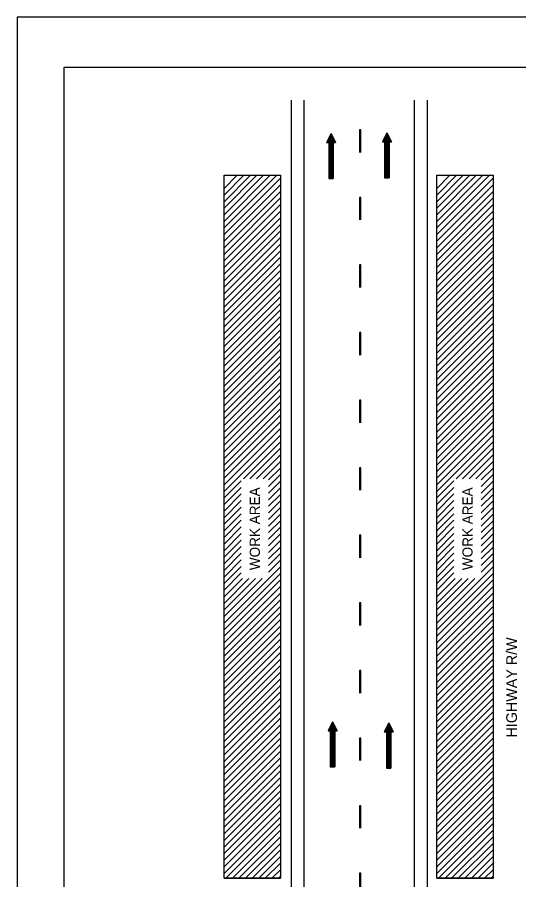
# Model space of a CAD drawing. Extents: x 1351 to 1567, y 178 to 457.
# Drawn here: x 1351.4 to 1459, y 271.7 to 456.9 of the extents above; entities that cross this region are included whole.
import ezdxf

# ---------------------------------------------------------------- set-up
doc = ezdxf.new("R2010")
doc.units = 0
for name, color, linetype in [('Level 10', 7, 'Continuous'), ('Level 2', 7, 'Continuous'), ('Level 60', 7, 'Continuous')]:
    doc.layers.add(name, color=color, linetype=linetype)

# ---------------------------------------------------------------- blocks, each defined once
blk = doc.blocks.new('C_LINE')
at = {"layer": 'Level 2'}
for p, q in [((-0.145, 237.062), (-0.145, 232.224)), ((0.145, 237.062), (-0.145, 237.062)), ((0.145, 232.224), (0.145, 237.062)), ((-0.145, 222.548), (-0.145, 217.71)), ((0.145, 222.548), (-0.145, 222.548)), ((0.145, 217.71), (0.145, 222.548)), ((-0.145, 208.034), (-0.145, 203.196)), ((0.145, 208.034), (-0.145, 208.034)), ((0.145, 203.196), (0.145, 208.034)), ((-0.145, 193.52), (-0.145, 188.682)), ((0.145, 193.52), (-0.145, 193.52)), ((0.145, 188.682), (0.145, 193.52)), ((-0.145, 179.006), (-0.145, 174.168)), ((0.145, 179.006), (-0.145, 179.006)), ((0.145, 174.168), (0.145, 179.006)), ((-0.145, 164.492), (-0.145, 159.654)), ((0.145, 164.492), (-0.145, 164.492)), ((0.145, 159.654), (0.145, 164.492)), ((-0.145, 149.978), (-0.145, 145.14)), ((0.145, 149.978), (-0.145, 149.978)), ((0.145, 145.14), (0.145, 149.978)), ((-0.145, 135.464), (-0.145, 130.626)), ((0.145, 135.464), (-0.145, 135.464)), ((0.145, 130.626), (0.145, 135.464)), ((-0.145, 120.95), (-0.145, 116.112)), ((0.145, 120.95), (-0.145, 120.95)), ((0.145, 116.112), (0.145, 120.95)), ((-0.145, 106.436), (-0.145, 101.598)), ((0.145, 106.436), (-0.145, 106.436)), ((0.145, 101.598), (0.145, 106.436)), ((-0.145, 91.922), (-0.145, 87.084)), ((0.145, 91.922), (-0.145, 91.922)), ((0.145, 87.084), (0.145, 91.922)), ((-0.145, 77.408), (-0.145, 72.57)), ((0.145, 77.408), (-0.145, 77.408)), ((0.145, 72.57), (0.145, 77.408))]:
    blk.add_line(p, q, dxfattribs=at)

msp = doc.modelspace()

# ---------------------------------------------------------------- linework, layer by layer
at = {"layer": 'Level 10'}
for p, q in [((1410.15, 439.12), (1410.15, 193.22)), ((1412.88, 439.12), (1412.88, 193.22)), ((1436.58, 439.12), (1436.58, 193.22)), ((1439.33, 439.12), (1439.33, 193.22)), ((1418.72, 431.99), (1417.75, 430.06)), ((1418.6, 431.75), (1418.6, 422.31)), ((1418.72, 431.99), (1418.72, 422.31)), ((1418.72, 431.99), (1419.68, 430.06)), ((1418.84, 431.75), (1418.84, 422.31)), ((1430.7, 432.12), (1429.74, 430.18)), ((1430.46, 431.63), (1430.46, 422.44)), ((1430.58, 431.87), (1430.58, 422.44)), ((1430.7, 432.12), (1430.7, 422.44)), ((1430.7, 432.12), (1431.67, 430.18)), ((1430.82, 431.87), (1430.82, 422.44)), ((1430.94, 431.63), (1430.94, 422.44)), ((1417.75, 430.06), (1418.23, 430.06)), ((1417.87, 430.3), (1417.87, 430.06)), ((1417.99, 430.54), (1417.99, 430.06)), ((1418.11, 430.78), (1418.11, 430.06)), ((1418.23, 431.02), (1418.23, 422.31)), ((1418.23, 430.06), (1418.23, 422.31)), ((1418.35, 431.26), (1418.35, 422.31)), ((1418.48, 431.51), (1418.48, 422.31)), ((1418.96, 431.51), (1418.96, 422.31)), ((1419.08, 431.26), (1419.08, 422.31)), ((1419.2, 431.02), (1419.2, 422.31)), ((1419.2, 430.06), (1419.2, 422.31)), ((1419.2, 430.06), (1419.68, 430.06)), ((1419.32, 430.78), (1419.32, 430.06)), ((1419.44, 430.54), (1419.44, 430.06)), ((1419.56, 430.3), (1419.56, 430.06)), ((1429.74, 430.18), (1430.22, 430.18)), ((1429.86, 430.42), (1429.86, 430.18)), ((1429.98, 430.66), (1429.98, 430.18)), ((1430.1, 430.91), (1430.1, 430.18)), ((1430.22, 431.15), (1430.22, 422.44)), ((1430.22, 430.18), (1430.22, 422.44)), ((1430.34, 431.39), (1430.34, 422.44)), ((1431.07, 431.39), (1431.07, 422.44)), ((1431.19, 431.15), (1431.19, 422.44)), ((1431.19, 430.18), (1431.19, 422.44)), ((1431.19, 430.18), (1431.67, 430.18)), ((1431.31, 430.91), (1431.31, 430.18)), ((1431.43, 430.66), (1431.43, 430.18)), ((1431.55, 430.42), (1431.55, 430.18)), ((1395.76, 420.15), (1398.59, 422.98)), ((1395.76, 418.74), (1400, 422.98)), ((1395.76, 417.32), (1401.41, 422.98)), ((1395.76, 415.91), (1402.83, 422.98)), ((1395.76, 414.5), (1404.24, 422.98)), ((1395.76, 413.08), (1405.66, 422.98)), ((1395.76, 411.67), (1407.07, 422.98)), ((1395.76, 410.25), (1407.85, 422.35)), ((1418.23, 422.31), (1419.2, 422.31)), ((1430.22, 422.44), (1431.19, 422.44)), ((1441.38, 420.15), (1444.21, 422.98)), ((1441.38, 418.74), (1445.63, 422.98)), ((1441.38, 417.32), (1447.04, 422.98)), ((1441.38, 415.91), (1448.46, 422.98)), ((1441.38, 414.5), (1449.87, 422.98)), ((1441.38, 413.08), (1451.28, 422.98)), ((1441.38, 411.67), (1452.7, 422.98)), ((1441.38, 410.25), (1453.48, 422.35)), ((1395.76, 408.84), (1407.85, 420.93)), ((1441.38, 408.84), (1453.48, 420.93)), ((1395.76, 407.43), (1407.85, 419.52)), ((1441.38, 407.43), (1453.48, 419.52)), ((1395.76, 406.01), (1407.85, 418.11)), ((1441.38, 406.01), (1453.48, 418.11)), ((1395.76, 404.6), (1407.85, 416.69)), ((1395.76, 403.18), (1407.85, 415.28)), ((1441.38, 404.6), (1453.48, 416.69)), ((1441.38, 403.18), (1453.48, 415.28)), ((1395.76, 401.77), (1407.85, 413.86)), ((1441.38, 401.77), (1453.48, 413.86)), ((1395.76, 400.35), (1407.85, 412.45)), ((1441.38, 400.35), (1453.48, 412.45)), ((1395.76, 398.94), (1407.85, 411.03)), ((1395.76, 397.53), (1407.85, 409.62)), ((1441.38, 398.94), (1453.48, 411.03)), ((1441.38, 397.53), (1453.48, 409.62)), ((1395.76, 396.11), (1407.85, 408.21)), ((1441.38, 396.11), (1453.48, 408.21)), ((1395.76, 394.7), (1407.85, 406.79)), ((1441.38, 394.7), (1453.48, 406.79)), ((1395.76, 393.28), (1407.85, 405.38)), ((1395.76, 391.87), (1407.85, 403.96)), ((1441.38, 393.28), (1453.48, 405.38)), ((1441.38, 391.87), (1453.48, 403.96)), ((1395.76, 390.45), (1407.85, 402.55)), ((1441.38, 390.45), (1453.48, 402.55)), ((1395.76, 389.04), (1407.85, 401.13)), ((1441.38, 389.04), (1453.48, 401.13)), ((1395.76, 387.63), (1407.85, 399.72)), ((1395.76, 386.21), (1407.85, 398.31)), ((1441.38, 387.63), (1453.48, 399.72)), ((1441.38, 386.21), (1453.48, 398.31)), ((1395.76, 384.8), (1407.85, 396.89)), ((1441.38, 384.8), (1453.48, 396.89)), ((1395.76, 383.38), (1407.85, 395.48)), ((1441.38, 383.38), (1453.48, 395.48)), ((1395.76, 381.97), (1407.85, 394.06)), ((1441.38, 381.97), (1453.48, 394.06)), ((1395.76, 380.56), (1407.85, 392.65)), ((1395.76, 379.14), (1407.85, 391.24)), ((1441.38, 380.56), (1453.48, 392.65)), ((1441.38, 379.14), (1453.48, 391.24)), ((1395.76, 377.73), (1407.85, 389.82)), ((1441.38, 377.73), (1453.48, 389.82)), ((1395.76, 376.31), (1407.85, 388.41)), ((1441.38, 376.31), (1453.48, 388.41)), ((1395.76, 374.9), (1407.85, 386.99)), ((1395.76, 373.48), (1407.85, 385.58)), ((1441.38, 374.9), (1453.48, 386.99)), ((1441.38, 373.48), (1453.48, 385.58)), ((1395.76, 372.07), (1407.85, 384.16)), ((1441.38, 372.07), (1453.48, 384.16)), ((1395.76, 370.66), (1407.85, 382.75)), ((1441.38, 370.66), (1453.48, 382.75)), ((1395.76, 369.24), (1407.85, 381.34)), ((1395.76, 367.83), (1407.85, 379.92)), ((1441.38, 369.24), (1453.48, 381.34)), ((1441.38, 367.83), (1453.48, 379.92)), ((1395.76, 366.41), (1407.85, 378.51)), ((1441.38, 366.41), (1453.48, 378.51)), ((1395.76, 365), (1407.85, 377.09)), ((1441.38, 365), (1453.48, 377.09)), ((1395.76, 363.58), (1407.85, 375.68)), ((1395.76, 362.17), (1407.85, 374.26)), ((1441.38, 363.58), (1453.48, 375.68)), ((1441.38, 362.17), (1453.48, 374.26)), ((1395.76, 360.76), (1407.85, 372.85)), ((1441.38, 360.76), (1453.48, 372.85)), ((1395.76, 359.34), (1407.85, 371.44)), ((1441.38, 359.34), (1453.48, 371.44)), ((1395.76, 357.93), (1407.85, 370.02)), ((1395.76, 356.51), (1407.85, 368.61)), ((1441.38, 357.93), (1453.48, 370.02)), ((1441.38, 356.51), (1453.48, 368.61)), ((1395.76, 355.1), (1407.85, 367.19)), ((1441.38, 355.1), (1453.48, 367.19)), ((1399.91, 357.83), (1407.85, 365.78)), ((1445.53, 357.83), (1453.48, 365.78)), ((1401.32, 357.83), (1407.85, 364.37)), ((1446.95, 357.83), (1453.48, 364.37)), ((1402.74, 357.83), (1407.85, 362.95)), ((1404.15, 357.83), (1407.85, 361.54)), ((1448.36, 357.83), (1453.48, 362.95)), ((1449.78, 357.83), (1453.48, 361.54)), ((1405.29, 357.56), (1407.85, 360.12)), ((1450.92, 357.56), (1453.48, 360.12)), ((1405.29, 356.14), (1407.85, 358.71)), ((1450.92, 356.14), (1453.48, 358.71)), ((1395.76, 353.69), (1399.45, 357.38)), ((1395.76, 352.27), (1399.45, 355.97)), ((1405.29, 354.73), (1407.85, 357.29)), ((1405.29, 353.32), (1407.85, 355.88)), ((1441.38, 353.69), (1445.08, 357.38)), ((1441.38, 352.27), (1445.08, 355.97)), ((1450.92, 354.73), (1453.48, 357.29)), ((1450.92, 353.32), (1453.48, 355.88)), ((1395.76, 350.86), (1399.45, 354.55)), ((1405.29, 351.9), (1407.85, 354.47)), ((1441.38, 350.86), (1445.08, 354.55)), ((1450.92, 351.9), (1453.48, 354.47)), ((1395.76, 349.44), (1399.45, 353.14)), ((1405.29, 350.49), (1407.85, 353.05)), ((1441.38, 349.44), (1445.08, 353.14)), ((1450.92, 350.49), (1453.48, 353.05)), ((1395.76, 348.03), (1399.45, 351.73)), ((1395.76, 346.61), (1399.45, 350.31)), ((1405.29, 349.07), (1407.85, 351.64)), ((1405.29, 347.66), (1407.85, 350.22)), ((1441.38, 348.03), (1445.08, 351.73)), ((1441.38, 346.61), (1445.08, 350.31)), ((1450.92, 349.07), (1453.48, 351.64)), ((1450.92, 347.66), (1453.48, 350.22)), ((1395.76, 345.2), (1399.45, 348.9)), ((1405.29, 346.25), (1407.85, 348.81)), ((1441.38, 345.2), (1445.08, 348.9)), ((1450.92, 346.25), (1453.48, 348.81)), ((1395.76, 343.79), (1399.45, 347.48)), ((1405.29, 344.83), (1407.85, 347.39)), ((1441.38, 343.79), (1445.08, 347.48)), ((1450.92, 344.83), (1453.48, 347.39)), ((1395.76, 342.37), (1399.45, 346.07)), ((1395.76, 340.96), (1399.45, 344.65)), ((1405.29, 343.42), (1407.85, 345.98)), ((1405.29, 342), (1407.85, 344.57)), ((1441.38, 342.37), (1445.08, 346.07)), ((1441.38, 340.96), (1445.08, 344.65)), ((1450.92, 343.42), (1453.48, 345.98)), ((1450.92, 342), (1453.48, 344.57)), ((1395.76, 339.54), (1399.45, 343.24)), ((1405.29, 340.59), (1407.85, 343.15)), ((1441.38, 339.54), (1445.08, 343.24)), ((1450.92, 340.59), (1453.48, 343.15)), ((1395.76, 338.13), (1399.45, 341.82)), ((1405.29, 339.18), (1407.85, 341.74)), ((1441.38, 338.13), (1445.08, 341.82)), ((1450.92, 339.18), (1453.48, 341.74)), ((1395.76, 336.71), (1399.45, 340.41)), ((1395.76, 335.3), (1399.45, 339)), ((1405.29, 337.76), (1407.85, 340.32)), ((1441.38, 336.71), (1445.08, 340.41)), ((1441.38, 335.3), (1445.08, 339)), ((1450.92, 337.76), (1453.48, 340.32)), ((1395.76, 326.81), (1407.85, 338.91)), ((1395.76, 333.89), (1399.45, 337.58)), ((1395.76, 325.4), (1407.85, 337.5)), ((1441.38, 326.81), (1453.48, 338.91)), ((1441.38, 333.89), (1445.08, 337.58)), ((1441.38, 325.4), (1453.48, 337.5)), ((1395.76, 332.47), (1399.7, 336.41)), ((1395.76, 331.06), (1401.11, 336.41)), ((1395.76, 329.64), (1402.53, 336.41)), ((1395.76, 328.23), (1403.94, 336.41)), ((1395.76, 323.99), (1407.85, 336.08)), ((1441.38, 332.47), (1445.33, 336.41)), ((1441.38, 331.06), (1446.74, 336.41)), ((1441.38, 329.64), (1448.16, 336.41)), ((1441.38, 328.23), (1449.57, 336.41)), ((1441.38, 323.99), (1453.48, 336.08)), ((1395.76, 322.57), (1407.85, 334.67)), ((1441.38, 322.57), (1453.48, 334.67)), ((1395.76, 321.16), (1407.85, 333.25)), ((1395.76, 319.74), (1407.85, 331.84)), ((1441.38, 321.16), (1453.48, 333.25)), ((1441.38, 319.74), (1453.48, 331.84)), ((1395.76, 318.33), (1407.85, 330.42)), ((1441.38, 318.33), (1453.48, 330.42)), ((1395.76, 316.92), (1407.85, 329.01)), ((1441.38, 316.92), (1453.48, 329.01)), ((1395.76, 315.5), (1407.85, 327.6)), ((1395.76, 314.09), (1407.85, 326.18)), ((1441.38, 315.5), (1453.48, 327.6)), ((1441.38, 314.09), (1453.48, 326.18)), ((1395.76, 312.67), (1407.85, 324.77)), ((1441.38, 312.67), (1453.48, 324.77)), ((1395.76, 311.26), (1407.85, 323.35)), ((1441.38, 311.26), (1453.48, 323.35)), ((1395.76, 309.84), (1407.85, 321.94)), ((1395.76, 308.43), (1407.85, 320.53)), ((1441.38, 309.84), (1453.48, 321.94)), ((1441.38, 308.43), (1453.48, 320.53)), ((1395.76, 307.01), (1407.85, 319.11)), ((1441.38, 307.01), (1453.48, 319.11)), ((1395.76, 305.6), (1407.85, 317.7)), ((1441.38, 305.6), (1453.48, 317.7)), ((1395.76, 304.19), (1407.85, 316.28)), ((1441.38, 304.19), (1453.48, 316.28)), ((1395.76, 302.77), (1407.85, 314.87)), ((1395.76, 301.36), (1407.85, 313.45)), ((1441.38, 302.77), (1453.48, 314.87)), ((1441.38, 301.36), (1453.48, 313.45)), ((1395.76, 299.94), (1407.85, 312.04)), ((1441.38, 299.94), (1453.48, 312.04)), ((1395.76, 298.53), (1407.85, 310.62)), ((1441.38, 298.53), (1453.48, 310.62)), ((1395.76, 297.12), (1407.85, 309.21)), ((1395.76, 295.7), (1407.85, 307.8)), ((1441.38, 297.12), (1453.48, 309.21)), ((1441.38, 295.7), (1453.48, 307.8)), ((1395.76, 294.29), (1407.85, 306.38)), ((1419.03, 305.64), (1418.07, 303.71)), ((1419.03, 305.64), (1419.03, 295.97)), ((1419.03, 305.64), (1420, 303.71)), ((1441.38, 294.29), (1453.48, 306.38)), ((1395.76, 292.87), (1407.85, 304.97)), ((1418.19, 303.95), (1418.19, 303.71)), ((1418.31, 304.19), (1418.31, 303.71)), ((1418.43, 304.43), (1418.43, 303.71)), ((1418.55, 304.67), (1418.55, 295.97)), ((1418.67, 304.92), (1418.67, 295.97)), ((1418.79, 305.16), (1418.79, 295.97)), ((1418.91, 305.4), (1418.91, 295.97)), ((1419.15, 305.4), (1419.15, 295.97)), ((1419.27, 305.16), (1419.27, 295.97)), ((1419.39, 304.92), (1419.39, 295.97)), ((1419.52, 304.67), (1419.52, 295.97)), ((1419.64, 304.43), (1419.64, 303.71)), ((1419.76, 304.19), (1419.76, 303.71)), ((1419.88, 303.95), (1419.88, 303.71)), ((1431.09, 305.38), (1430.12, 303.44)), ((1430.37, 303.93), (1430.37, 303.44)), ((1430.49, 304.17), (1430.49, 303.44)), ((1430.61, 304.41), (1430.61, 295.7)), ((1430.73, 304.65), (1430.73, 295.7)), ((1430.85, 304.89), (1430.85, 295.7)), ((1430.97, 305.13), (1430.97, 295.7)), ((1431.09, 305.38), (1431.09, 295.7)), ((1431.09, 305.38), (1432.06, 303.44)), ((1431.21, 305.13), (1431.21, 295.7)), ((1431.33, 304.89), (1431.33, 295.7)), ((1431.45, 304.65), (1431.45, 295.7)), ((1431.58, 304.41), (1431.58, 295.7)), ((1431.7, 304.17), (1431.7, 303.44)), ((1431.82, 303.93), (1431.82, 303.44)), ((1441.38, 292.87), (1453.48, 304.97)), ((1395.76, 291.46), (1407.85, 303.55)), ((1395.76, 290.05), (1407.85, 302.14)), ((1418.07, 303.71), (1418.55, 303.71)), ((1418.55, 303.71), (1418.55, 295.97)), ((1419.52, 303.71), (1419.52, 295.97)), ((1419.52, 303.71), (1420, 303.71)), ((1430.12, 303.44), (1430.61, 303.44)), ((1430.25, 303.68), (1430.25, 303.44)), ((1430.61, 303.44), (1430.61, 295.7)), ((1431.58, 303.44), (1431.58, 295.7)), ((1431.58, 303.44), (1432.06, 303.44)), ((1431.94, 303.68), (1431.94, 303.44)), ((1441.38, 291.46), (1453.48, 303.55)), ((1441.38, 290.05), (1453.48, 302.14)), ((1395.76, 288.63), (1407.85, 300.73)), ((1441.38, 288.63), (1453.48, 300.73)), ((1395.76, 287.22), (1407.85, 299.31)), ((1441.38, 287.22), (1453.48, 299.31)), ((1395.76, 285.8), (1407.85, 297.9)), ((1395.76, 284.39), (1407.85, 296.48)), ((1441.38, 285.8), (1453.48, 297.9)), ((1441.38, 284.39), (1453.48, 296.48)), ((1395.76, 282.97), (1407.85, 295.07)), ((1418.55, 295.97), (1419.52, 295.97)), ((1430.61, 295.7), (1431.58, 295.7)), ((1441.38, 282.97), (1453.48, 295.07)), ((1395.76, 281.56), (1407.85, 293.66)), ((1441.38, 281.56), (1453.48, 293.66)), ((1395.76, 280.14), (1407.85, 292.24)), ((1395.76, 278.73), (1407.85, 290.83)), ((1441.38, 280.14), (1453.48, 292.24)), ((1441.38, 278.73), (1453.48, 290.83)), ((1395.76, 277.32), (1407.85, 289.41)), ((1441.38, 277.32), (1453.48, 289.41)), ((1395.76, 275.9), (1407.85, 288)), ((1441.38, 275.9), (1453.48, 288)), ((1395.76, 274.49), (1407.85, 286.58)), ((1441.38, 274.49), (1453.48, 286.58)), ((1395.76, 273.07), (1407.85, 285.17)), ((1396.14, 272.04), (1407.85, 283.75)), ((1441.38, 273.07), (1453.48, 285.17)), ((1441.77, 272.04), (1453.48, 283.75)), ((1397.55, 272.04), (1407.85, 282.34)), ((1443.18, 272.04), (1453.48, 282.34)), ((1398.96, 272.04), (1407.85, 280.93)), ((1444.59, 272.04), (1453.48, 280.93)), ((1400.38, 272.04), (1407.85, 279.51)), ((1401.79, 272.04), (1407.85, 278.1)), ((1446.01, 272.04), (1453.48, 279.51)), ((1447.42, 272.04), (1453.48, 278.1)), ((1403.21, 272.04), (1407.85, 276.68)), ((1448.84, 272.04), (1453.48, 276.68)), ((1404.62, 272.04), (1407.85, 275.27)), ((1450.25, 272.04), (1453.48, 275.27)), ((1406.04, 272.04), (1407.85, 273.86)), ((1407.45, 272.04), (1407.85, 272.44)), ((1451.66, 272.04), (1453.48, 273.86)), ((1453.08, 272.04), (1453.48, 272.44))]:
    msp.add_line(p, q, dxfattribs=at)
at = {"layer": 'Level 60'}
for p, q in [((1395.76, 422.98), (1407.85, 422.98)), ((1441.38, 422.98), (1453.48, 422.98)), ((1395.76, 272.04), (1407.85, 272.04)), ((1441.38, 272.04), (1453.48, 272.04))]:
    msp.add_line(p, q, dxfattribs=at)
for points in [[(1567.41, 456.92), (1351.41, 456.92), (1351.41, 177.92), (1567.41, 177.92)], [(1548.28, 446.11), (1361.41, 446.11), (1361.41, 188.73), (1548.28, 188.73)], [(1395.76, 422.98), (1407.85, 422.98), (1407.85, 272.04), (1395.76, 272.04)], [(1441.38, 422.98), (1453.48, 422.98), (1453.48, 272.04), (1441.38, 272.04)]]:
    msp.add_lwpolyline(points, close=True, dxfattribs=at)

# ---------------------------------------------------------------- block references
at = {"layer": 'Level 2'}
msp.add_blockref('C_LINE', (1424.96, 195.69), dxfattribs=at)

# ---------------------------------------------------------------- texts
at = {"layer": 'Level 10'}
for s, height, p in [('WORK AREA', 2.177, (1403.45, 338.18)), ('WORK AREA', 2.177, (1449.08, 338.18)), ('HIGHWAY R/W', 2.298, (1458.6, 302.25))]:
    msp.add_text(s, height=height, rotation=90, dxfattribs=at).set_placement(p)

doc.saveas('drawing.dxf')
